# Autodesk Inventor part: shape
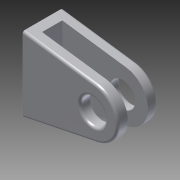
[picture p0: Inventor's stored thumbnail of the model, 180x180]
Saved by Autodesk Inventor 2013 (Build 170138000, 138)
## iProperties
Created: 2009-11
Part Number: shape
Document SubType Name: Modeling
Designer: pokornp
Density: 1 g/cm^3
Mass: 9216 g
Surface Area: 5440 cm^2
Volume: 9216 cm^3
Material: Generic
Author: pokornp
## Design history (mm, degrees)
sketch "Sketch1"
  geometry: L1 (0, 0)-(0, -160); L2 (0, -160)-(400, -160); L3 (400, -160)-(400, -120); L4 (400, -120)-(40, -120); L5 (40, -120)-(40, -40); L6 (40, -40)-(400, -40); L7 (400, -40)-(400, 0); L8 (400, 0)-(0, 0)
  constraints: 16 end point, 6 parallel, 1 perpendicular, 1 vertical, 1 vertical alignment
  dimensions: "w" = 160 distance of L1.start L1.end; "d1" = 80 distance of L4.end L5.end (= 0.5 x w); "d2" = 40 distance of L2.end L3.end (= 0.25 x w); "d3" = 40 distance between parallel lines of L1 L5 (= 0.25 x w); "d4" = 400 distance of L1.end L2.end (= 2.5 x w)
extrude "Extrusion1" new body sketch "Sketch1" distance "d5" = 320 (= 2 x w); taper "d6" = 0 deg
hole "Hole1" diameter "d9" = 100; stored, may be unused: countersink angle "d13" = 90 deg, drill point angle "d15" = 118 deg; dims "d7" = 120, "d8" = 150, "d10" = 6, "d11" = 4, "d12" = 2, "d14" = 8
fillet "Fillet1" dims "d16" = 50
fillet "Fillet2" dims "d17" = 10
sketch "Sketch2"
  geometry: L1 (0, 0)-(0, -300) reference; L2 (0, -300)-(293.656, -259.831); L3 (0, 0)-(300.154, -61.275); A1 r 100.761 centre (280, -160) between (293.656, -259.831) and (300.154, -61.275); 1 further point
  constraints: 4 end point, 2 point on circle, 2 tangent, 1 centre point
extrude "Extrusion2" sketch "Sketch2" stored distance "d18" = 320 (= 2 x w); taper "d19" = 0 deg
fillet "Fillet3" dims "d20" = 10
fillet "Fillet5" dims "d22" = 5
body "Solid1"
